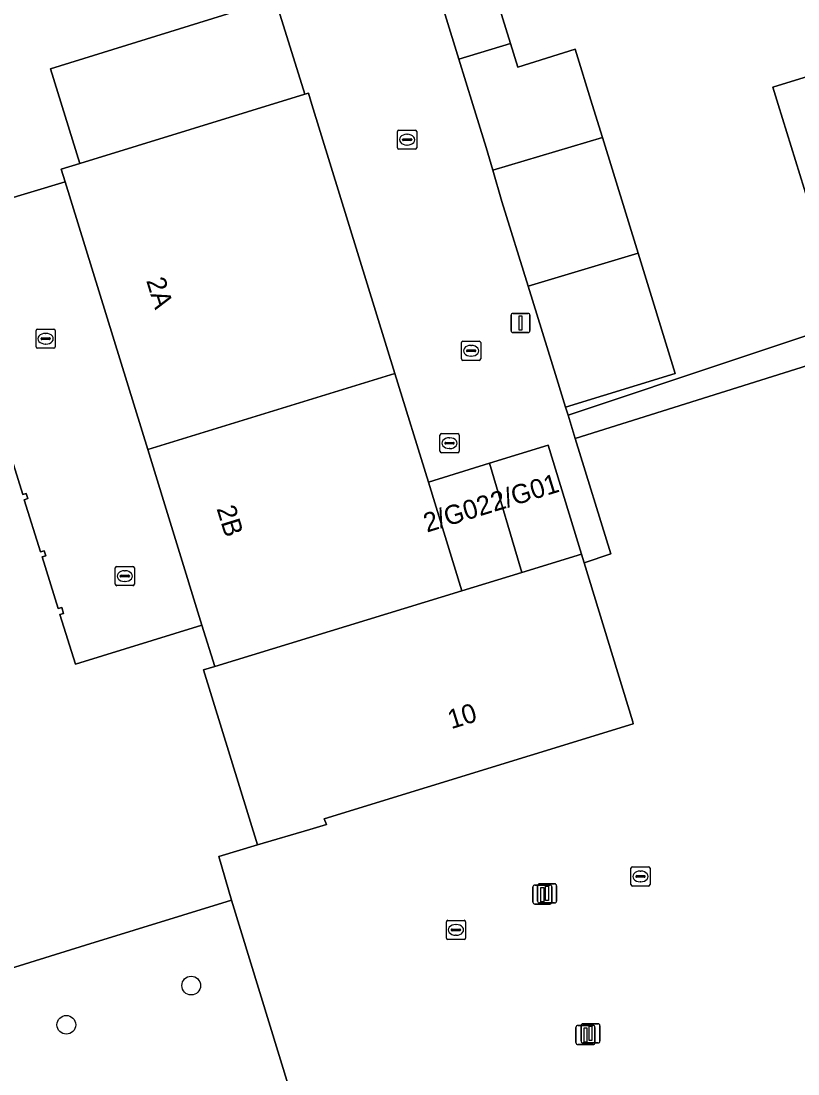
# Model space of a CAD drawing. Extents: x 161248 to 161848, y 384871 to 385383.
# Drawn here: x 161449.7 to 161490.3, y 384949.3 to 385004.4 of the extents above; entities that cross this region are included whole.
import ezdxf

# ---------------------------------------------------------------- set-up
doc = ezdxf.new("R2010")
doc.units = 0
for name, color, linetype in [('IMGEO_Boom', 7, 'Continuous'), ('IMGEO_Brandkraan', 7, 'Continuous'), ('IMGEO_Erf', 7, 'Continuous'), ('IMGEO_Groenvoorziening', 7, 'Continuous'), ('IMGEO_Hek', 7, 'Continuous'), ('IMGEO_Kolk', 7, 'Continuous'), ('IMGEO_Lichtmast', 7, 'Continuous'), ('IMGEO_Pand', 7, 'Continuous'), ('IMGEO_Pand_nummerreeks', 7, 'Continuous'), ('IMGEO_Parkeervlak_open', 7, 'Continuous'), ('IMGEO_Rijbaan_lokaal_open', 7, 'Continuous'), ('IMGEO_Voetpad_open', 7, 'Continuous')]:
    doc.layers.add(name, color=color, linetype=linetype)

msp = doc.modelspace()

# ---------------------------------------------------------------- linework, layer by layer
at = {"layer": 'IMGEO_Boom'}
for centre in [(161458.625, 384953.929), (161452.098, 384951.877)]:
    msp.add_circle(centre, 0.489, dxfattribs=at)
at = {"layer": 'IMGEO_Brandkraan'}
for p, q in [((161471.63, 384981.861), (161471.63, 384982.713)), ((161471.705, 384982.787), (161472.557, 384982.787)), ((161471.932, 384982.33), (161472.33, 384982.33)), ((161472.118, 384982.567), (161472.143, 384982.567)), ((161472.631, 384982.713), (161472.631, 384981.861)), ((161472.557, 384981.787), (161471.705, 384981.787)), ((161471.889, 384982.281), (161471.889, 384982.293)), ((161472.327, 384982.244), (161471.929, 384982.244)), ((161472.141, 384982.007), (161472.116, 384982.007)), ((161472.373, 384982.293), (161472.373, 384982.281))]:
    msp.add_line(p, q, dxfattribs=at)
for points in [[(161471.63, 384981.861), (161471.63, 384982.713)], [(161471.705, 384982.787), (161472.557, 384982.787)], [(161472.631, 384982.713), (161472.631, 384981.861)], [(161472.557, 384981.787), (161471.705, 384981.787)]]:
    msp.add_lwpolyline(points, dxfattribs=at)
for centre, radius, start, end in [((161471.707, 384982.711), 0.0765, 91.552, 178.448), ((161471.707, 384982.711), 0.0765, 91.552, 178.448), ((161471.929, 384982.29), 0.0403, 85.8775, 175.7526), ((161472.334, 384982.292), 0.0386, 1.7309, 96.639), ((161472.555, 384982.711), 0.0765, 1.552, 88.448), ((161472.555, 384982.711), 0.0765, 1.552, 88.448), ((161471.707, 384981.863), 0.0765, 181.552, 268.448), ((161471.707, 384981.863), 0.0765, 181.552, 268.448), ((161471.926, 384982.28), 0.0366, 178.938, 274.7102), ((161472.33, 384982.287), 0.043, 264.8664, 352.4533), ((161472.555, 384981.863), 0.0765, 271.552, 358.448), ((161472.555, 384981.863), 0.0765, 271.552, 358.448)]:
    msp.add_arc(centre, radius, start, end, dxfattribs=at)
for centre, major_axis, ratio, start_param, end_param in [((161472.117, 384982.287), (-0.387, 0.002), 0.722429, 4.712389, 7.853982), ((161472.142, 384982.287), (-0.39, 0.002), 0.717154, 1.570796, 4.712389)]:
    msp.add_ellipse(centre, major_axis=major_axis, ratio=ratio, start_param=start_param, end_param=end_param, dxfattribs=at)
at = {"layer": 'IMGEO_Erf'}
msp.add_lwpolyline([(161489.033, 385000.893), (161492.311, 385001.903), (161490.476, 385007.857), (161488.521, 385014.203), (161470.742, 385008.465), (161471.18, 385007.012), (161473.878, 385007.844), (161475.314, 385003.189), (161475.695, 385001.953), (161478.707, 385002.877), (161479.593, 385000), (161480.125, 384998.272), (161481.988, 384992.224), (161483.928, 384985.929), (161478.198, 384984.164), (161478.327, 384983.747), (161496.079, 384989.672), (161493.374, 384988.838), (161491.462, 384995.042), (161490.89, 384994.866), (161489.308, 385000)], close=True, dxfattribs=at)
msp.add_lwpolyline([(161504.48, 384990.635), (161478.706, 384982.523), (161480.569, 384976.5), (161479.172, 384976.026), (161481.71, 384967.719), (161481.734, 384967.62), (161465.577, 384962.651), (161465.703, 384962.356), (161464.826, 384962.094), (161462.094, 384961.279), (161460.068, 384960.675), (161460.725, 384958.4), (161468.671, 384932.496), (161456.058, 384928.282), (161456.306, 384927.519), (161458.229, 384921.594), (161459.445, 384917.85), (161459.563, 384917.873), (161460.304, 384915.459), (161465.803, 384917.137), (161465.842, 384917.432), (161470.469, 384917.199), (161473.166, 384917.063), (161500, 384915.713)], dxfattribs=at)
at = {"layer": 'IMGEO_Groenvoorziening'}
msp.add_lwpolyline([(161456.306, 384927.519), (161456.058, 384928.282), (161468.671, 384932.496), (161460.725, 384958.4), (161453.097, 384956.043), (161448.319, 384954.566), (161445.755, 384950.228), (161446.432, 384949.557), (161447.081, 384948.789), (161447.66, 384947.966), (161448.163, 384947.095), (161448.585, 384946.183), (161448.925, 384945.236), (161454.217, 384928.071), (161455.63, 384928.386), (161455.957, 384927.409)], close=True, dxfattribs=at)
at = {"layer": 'IMGEO_Hek'}
msp.add_lwpolyline([(161452.034, 384995.958), (161445.368, 384993.944)], dxfattribs=at)
at = {"layer": 'IMGEO_Kolk'}
for p, q in [((161469.413, 384997.728), (161469.413, 384998.58)), ((161469.488, 384998.654), (161470.34, 384998.654)), ((161469.901, 384998.434), (161469.926, 384998.434)), ((161470.414, 384998.58), (161470.414, 384997.728)), ((161469.672, 384998.148), (161469.672, 384998.16)), ((161470.11, 384998.111), (161469.712, 384998.111)), ((161469.715, 384998.197), (161470.113, 384998.197)), ((161469.924, 384997.874), (161469.899, 384997.874)), ((161470.156, 384998.16), (161470.156, 384998.148)), ((161470.34, 384997.654), (161469.488, 384997.654)), ((161450.516, 384987.322), (161450.516, 384988.174)), ((161450.591, 384988.248), (161451.443, 384988.248)), ((161451.004, 384988.028), (161451.029, 384988.028)), ((161451.517, 384988.174), (161451.517, 384987.322)), ((161450.775, 384987.742), (161450.775, 384987.754)), ((161451.213, 384987.705), (161450.815, 384987.705)), ((161450.818, 384987.791), (161451.216, 384987.791)), ((161451.027, 384987.468), (161451.002, 384987.468)), ((161451.259, 384987.754), (161451.259, 384987.742)), ((161472.758, 384986.689), (161472.758, 384987.541)), ((161472.833, 384987.615), (161473.685, 384987.615)), ((161473.246, 384987.395), (161473.271, 384987.395)), ((161473.759, 384987.541), (161473.759, 384986.689)), ((161451.443, 384987.248), (161450.591, 384987.248)), ((161473.017, 384987.109), (161473.017, 384987.121)), ((161473.455, 384987.072), (161473.057, 384987.072)), ((161473.06, 384987.158), (161473.458, 384987.158)), ((161473.269, 384986.835), (161473.244, 384986.835)), ((161473.501, 384987.121), (161473.501, 384987.109)), ((161473.685, 384986.615), (161472.833, 384986.615)), ((161454.655, 384974.911), (161454.655, 384975.763)), ((161454.73, 384975.837), (161455.582, 384975.837)), ((161455.656, 384975.763), (161455.656, 384974.911)), ((161454.914, 384975.331), (161454.914, 384975.343)), ((161455.352, 384975.294), (161454.954, 384975.294)), ((161454.957, 384975.38), (161455.355, 384975.38)), ((161455.143, 384975.617), (161455.168, 384975.617)), ((161455.398, 384975.343), (161455.398, 384975.331)), ((161455.582, 384974.837), (161454.73, 384974.837)), ((161455.166, 384975.057), (161455.141, 384975.057)), ((161481.613, 384959.207), (161481.613, 384960.059)), ((161481.688, 384960.133), (161482.54, 384960.133)), ((161482.101, 384959.913), (161482.126, 384959.913)), ((161482.614, 384960.059), (161482.614, 384959.207)), ((161481.872, 384959.627), (161481.872, 384959.639)), ((161482.31, 384959.59), (161481.912, 384959.59)), ((161481.915, 384959.676), (161482.313, 384959.676)), ((161482.124, 384959.353), (161482.099, 384959.353)), ((161482.356, 384959.639), (161482.356, 384959.627)), ((161482.54, 384959.133), (161481.688, 384959.133)), ((161471.965, 384956.414), (161471.965, 384957.266)), ((161472.04, 384957.34), (161472.892, 384957.34)), ((161472.453, 384957.12), (161472.478, 384957.12)), ((161472.966, 384957.266), (161472.966, 384956.414)), ((161472.224, 384956.834), (161472.224, 384956.846)), ((161472.662, 384956.797), (161472.264, 384956.797)), ((161472.267, 384956.883), (161472.665, 384956.883)), ((161472.476, 384956.56), (161472.451, 384956.56)), ((161472.708, 384956.846), (161472.708, 384956.834)), ((161472.892, 384956.34), (161472.04, 384956.34))]:
    msp.add_line(p, q, dxfattribs=at)
for points in [[(161469.413, 384997.728), (161469.413, 384998.58)], [(161469.488, 384998.654), (161470.34, 384998.654)], [(161470.414, 384998.58), (161470.414, 384997.728)], [(161470.34, 384997.654), (161469.488, 384997.654)], [(161450.516, 384987.322), (161450.516, 384988.174)], [(161450.591, 384988.248), (161451.443, 384988.248)], [(161451.517, 384988.174), (161451.517, 384987.322)], [(161472.758, 384986.689), (161472.758, 384987.541)], [(161472.833, 384987.615), (161473.685, 384987.615)], [(161473.759, 384987.541), (161473.759, 384986.689)], [(161451.443, 384987.248), (161450.591, 384987.248)], [(161473.685, 384986.615), (161472.833, 384986.615)], [(161454.655, 384974.911), (161454.655, 384975.763)], [(161454.73, 384975.837), (161455.582, 384975.837)], [(161455.656, 384975.763), (161455.656, 384974.911)], [(161455.582, 384974.837), (161454.73, 384974.837)], [(161481.613, 384959.207), (161481.613, 384960.059)], [(161481.688, 384960.133), (161482.54, 384960.133)], [(161482.614, 384960.059), (161482.614, 384959.207)], [(161482.54, 384959.133), (161481.688, 384959.133)], [(161471.965, 384956.414), (161471.965, 384957.266)], [(161472.04, 384957.34), (161472.892, 384957.34)], [(161472.966, 384957.266), (161472.966, 384956.414)], [(161472.892, 384956.34), (161472.04, 384956.34)]]:
    msp.add_lwpolyline(points, dxfattribs=at)
for centre, radius, start, end in [((161469.49, 384998.578), 0.0765, 91.552, 178.448), ((161469.49, 384998.578), 0.0765, 91.552, 178.448), ((161470.338, 384998.578), 0.0765, 1.552, 88.448), ((161470.338, 384998.578), 0.0765, 1.552, 88.448), ((161469.712, 384998.157), 0.0403, 85.8775, 175.7526), ((161469.709, 384998.147), 0.0366, 178.938, 274.7102), ((161470.113, 384998.154), 0.043, 264.8664, 352.4533), ((161470.117, 384998.159), 0.0386, 1.7309, 96.639), ((161469.49, 384997.73), 0.0765, 181.552, 268.448), ((161469.49, 384997.73), 0.0765, 181.552, 268.448), ((161470.338, 384997.73), 0.0765, 271.552, 358.448), ((161470.338, 384997.73), 0.0765, 271.552, 358.448), ((161450.593, 384988.172), 0.0765, 91.552, 178.448), ((161450.593, 384988.172), 0.0765, 91.552, 178.448), ((161451.441, 384988.172), 0.0765, 1.552, 88.448), ((161451.441, 384988.172), 0.0765, 1.552, 88.448), ((161450.593, 384987.324), 0.0765, 181.552, 268.448), ((161450.593, 384987.324), 0.0765, 181.552, 268.448), ((161450.815, 384987.751), 0.0403, 85.8775, 175.7526), ((161450.812, 384987.741), 0.0366, 178.938, 274.7102), ((161451.216, 384987.748), 0.043, 264.8664, 352.4533), ((161451.22, 384987.753), 0.0386, 1.7309, 96.639), ((161451.441, 384987.324), 0.0765, 271.552, 358.448), ((161451.441, 384987.324), 0.0765, 271.552, 358.448), ((161472.835, 384987.539), 0.0765, 91.552, 178.448), ((161472.835, 384987.539), 0.0765, 91.552, 178.448), ((161473.683, 384987.539), 0.0765, 1.552, 88.448), ((161473.683, 384987.539), 0.0765, 1.552, 88.448), ((161473.057, 384987.118), 0.0403, 85.8775, 175.7526), ((161473.054, 384987.108), 0.0366, 178.938, 274.7102), ((161473.458, 384987.115), 0.043, 264.8664, 352.4533), ((161473.462, 384987.12), 0.0386, 1.7309, 96.639), ((161472.835, 384986.691), 0.0765, 181.552, 268.448), ((161472.835, 384986.691), 0.0765, 181.552, 268.448), ((161473.683, 384986.691), 0.0765, 271.552, 358.448), ((161473.683, 384986.691), 0.0765, 271.552, 358.448), ((161454.732, 384975.761), 0.0765, 91.552, 178.448), ((161454.732, 384975.761), 0.0765, 91.552, 178.448), ((161455.58, 384975.761), 0.0765, 1.552, 88.448), ((161455.58, 384975.761), 0.0765, 1.552, 88.448), ((161454.954, 384975.34), 0.0403, 85.8775, 175.7526), ((161454.951, 384975.33), 0.0366, 178.938, 274.7102), ((161455.355, 384975.337), 0.043, 264.8664, 352.4533), ((161455.359, 384975.342), 0.0386, 1.7309, 96.639), ((161454.732, 384974.913), 0.0765, 181.552, 268.448), ((161454.732, 384974.913), 0.0765, 181.552, 268.448), ((161455.58, 384974.913), 0.0765, 271.552, 358.448), ((161455.58, 384974.913), 0.0765, 271.552, 358.448), ((161481.69, 384960.057), 0.0765, 91.552, 178.448), ((161481.69, 384960.057), 0.0765, 91.552, 178.448), ((161482.538, 384960.057), 0.0765, 1.552, 88.448), ((161482.538, 384960.057), 0.0765, 1.552, 88.448), ((161481.69, 384959.209), 0.0765, 181.552, 268.448), ((161481.69, 384959.209), 0.0765, 181.552, 268.448), ((161481.912, 384959.636), 0.0403, 85.8775, 175.7526), ((161481.909, 384959.626), 0.0366, 178.938, 274.7102), ((161482.313, 384959.633), 0.043, 264.8664, 352.4533), ((161482.317, 384959.638), 0.0386, 1.7309, 96.639), ((161482.538, 384959.209), 0.0765, 271.552, 358.448), ((161482.538, 384959.209), 0.0765, 271.552, 358.448), ((161472.042, 384957.264), 0.0765, 91.552, 178.448), ((161472.042, 384957.264), 0.0765, 91.552, 178.448), ((161472.89, 384957.264), 0.0765, 1.552, 88.448), ((161472.89, 384957.264), 0.0765, 1.552, 88.448), ((161472.264, 384956.843), 0.0403, 85.8775, 175.7526), ((161472.261, 384956.833), 0.0366, 178.938, 274.7102), ((161472.665, 384956.84), 0.043, 264.8664, 352.4533), ((161472.669, 384956.845), 0.0386, 1.7309, 96.639), ((161472.042, 384956.416), 0.0765, 181.552, 268.448), ((161472.042, 384956.416), 0.0765, 181.552, 268.448), ((161472.89, 384956.416), 0.0765, 271.552, 358.448), ((161472.89, 384956.416), 0.0765, 271.552, 358.448)]:
    msp.add_arc(centre, radius, start, end, dxfattribs=at)
for centre, major_axis, ratio, start_param, end_param in [((161469.9, 384998.154), (-0.387, 0.002), 0.722429, 4.712389, 7.853982), ((161469.925, 384998.154), (-0.39, 0.002), 0.717154, 1.570796, 4.712389), ((161451.003, 384987.748), (-0.387, 0.002), 0.722429, 4.712389, 7.853982), ((161451.028, 384987.748), (-0.39, 0.002), 0.717154, 1.570796, 4.712389), ((161473.245, 384987.115), (-0.387, 0.002), 0.722429, 4.712389, 7.853982), ((161473.27, 384987.115), (-0.39, 0.002), 0.717154, 1.570796, 4.712389), ((161455.142, 384975.337), (-0.387, 0.002), 0.722429, 4.712389, 7.853982), ((161455.167, 384975.337), (-0.39, 0.002), 0.717154, 1.570796, 4.712389), ((161482.1, 384959.633), (-0.387, 0.002), 0.722429, 4.712389, 7.853982), ((161482.125, 384959.633), (-0.39, 0.002), 0.717154, 1.570796, 4.712389), ((161472.452, 384956.84), (-0.387, 0.002), 0.722429, 4.712389, 7.853982), ((161472.477, 384956.84), (-0.39, 0.002), 0.717154, 1.570796, 4.712389)]:
    msp.add_ellipse(centre, major_axis=major_axis, ratio=ratio, start_param=start_param, end_param=end_param, dxfattribs=at)
at = {"layer": 'IMGEO_Lichtmast'}
for p, q in [((161475.347, 384988.172), (161475.347, 384988.972)), ((161475.347, 384988.972), (161475.347, 384988.172)), ((161475.447, 384989.072), (161476.237, 384989.072)), ((161476.237, 384989.072), (161475.447, 384989.072)), ((161476.337, 384988.972), (161476.337, 384988.172)), ((161476.337, 384988.172), (161476.337, 384988.972)), ((161476.237, 384988.072), (161475.447, 384988.072)), ((161475.447, 384988.072), (161476.237, 384988.072)), ((161476.834, 384959.25), (161477.624, 384959.25)), ((161477.624, 384959.25), (161476.834, 384959.25)), ((161476.491, 384958.287), (161476.491, 384959.087)), ((161476.491, 384959.087), (161476.491, 384958.287)), ((161476.591, 384959.187), (161477.381, 384959.187)), ((161477.381, 384959.187), (161476.591, 384959.187)), ((161476.734, 384958.35), (161476.734, 384959.15)), ((161476.734, 384959.15), (161476.734, 384958.35)), ((161477.481, 384959.087), (161477.481, 384958.287)), ((161477.481, 384958.287), (161477.481, 384959.087)), ((161477.724, 384959.15), (161477.724, 384958.35)), ((161477.724, 384958.35), (161477.724, 384959.15)), ((161477.381, 384958.187), (161476.591, 384958.187)), ((161476.591, 384958.187), (161477.381, 384958.187)), ((161477.624, 384958.25), (161476.834, 384958.25)), ((161476.834, 384958.25), (161477.624, 384958.25)), ((161478.741, 384950.945), (161478.741, 384951.745)), ((161478.741, 384951.745), (161478.741, 384950.945)), ((161478.841, 384951.845), (161479.631, 384951.845)), ((161479.631, 384951.845), (161478.841, 384951.845)), ((161479.004, 384951.032), (161479.004, 384951.832)), ((161479.004, 384951.832), (161479.004, 384951.032)), ((161479.104, 384951.932), (161479.894, 384951.932)), ((161479.894, 384951.932), (161479.104, 384951.932)), ((161479.731, 384951.745), (161479.731, 384950.945)), ((161479.731, 384950.945), (161479.731, 384951.745)), ((161479.994, 384951.832), (161479.994, 384951.032)), ((161479.994, 384951.032), (161479.994, 384951.832)), ((161479.631, 384950.845), (161478.841, 384950.845)), ((161478.841, 384950.845), (161479.631, 384950.845)), ((161479.894, 384950.932), (161479.104, 384950.932)), ((161479.104, 384950.932), (161479.894, 384950.932))]:
    msp.add_line(p, q, dxfattribs=at)
for points in [[(161475.767, 384988.947), (161475.917, 384988.947), (161475.917, 384988.197), (161475.767, 384988.197), (161475.767, 384988.947)], [(161476.911, 384959.062), (161477.061, 384959.062), (161477.061, 384958.312), (161476.911, 384958.312), (161476.911, 384959.062)], [(161477.154, 384959.125), (161477.304, 384959.125), (161477.304, 384958.375), (161477.154, 384958.375), (161477.154, 384959.125)], [(161479.161, 384951.72), (161479.311, 384951.72), (161479.311, 384950.97), (161479.161, 384950.97), (161479.161, 384951.72)], [(161479.424, 384951.807), (161479.574, 384951.807), (161479.574, 384951.057), (161479.424, 384951.057), (161479.424, 384951.807)]]:
    msp.add_lwpolyline(points, dxfattribs=at)
for centre, start, end in [((161475.447, 384988.972), 90, 180), ((161475.447, 384988.972), 90, 180), ((161476.237, 384988.972), 0, 90), ((161476.237, 384988.972), 360, 90), ((161475.447, 384988.172), 180, 270), ((161475.447, 384988.172), 180, 270), ((161476.237, 384988.172), 270, 0), ((161476.237, 384988.172), 270, 0), ((161476.834, 384959.15), 90, 180), ((161476.834, 384959.15), 90, 180), ((161477.624, 384959.15), 0, 90), ((161477.624, 384959.15), 360, 90), ((161476.591, 384959.087), 90, 180), ((161476.591, 384959.087), 90, 180), ((161477.381, 384959.087), 0, 90), ((161477.381, 384959.087), 360, 90), ((161476.591, 384958.287), 180, 270), ((161476.591, 384958.287), 180, 270), ((161476.834, 384958.35), 180, 270), ((161476.834, 384958.35), 180, 270), ((161477.381, 384958.287), 270, 0), ((161477.381, 384958.287), 270, 0), ((161477.624, 384958.35), 270, 0), ((161477.624, 384958.35), 270, 0), ((161478.841, 384951.745), 90, 180), ((161478.841, 384951.745), 90, 180), ((161479.104, 384951.832), 90, 180), ((161479.104, 384951.832), 90, 180), ((161479.631, 384951.745), 0, 90), ((161479.631, 384951.745), 360, 90), ((161479.894, 384951.832), 0, 90), ((161479.894, 384951.832), 360, 90), ((161478.841, 384950.945), 180, 270), ((161478.841, 384950.945), 180, 270), ((161479.104, 384951.032), 180, 270), ((161479.104, 384951.032), 180, 270), ((161479.631, 384950.945), 270, 0), ((161479.631, 384950.945), 270, 0), ((161479.894, 384951.032), 270, 0), ((161479.894, 384951.032), 270, 0)]:
    msp.add_arc(centre, 0.1, start, end, dxfattribs=at)
at = {"layer": 'IMGEO_Pand'}
for points in [[(161472.616, 385002.358), (161475.314, 385003.189), (161473.878, 385007.844), (161471.18, 385007.012)], [(161501.619, 385000), (161500.299, 385004.283), (161500, 385004.194), (161492.311, 385001.903), (161489.033, 385000.893), (161489.308, 385000), (161490.89, 384994.866), (161491.462, 384995.042), (161494.168, 384995.875), (161500, 384997.623), (161502.147, 384998.285)], [(161473.343, 385000), (161474.039, 384997.742), (161474.387, 384996.562), (161480.125, 384998.272), (161479.593, 385000), (161478.707, 385002.877), (161475.695, 385001.953), (161475.314, 385003.189), (161472.616, 385002.358)], [(161464.932, 385000), (161464.749, 385000.592), (161464.574, 385000.538), (161452.809, 384996.909), (161451.834, 384996.608), (161452.034, 384995.958), (161456.356, 384981.952), (161469.271, 384985.935)], [(161474.872, 384994.919), (161476.238, 384990.501), (161481.988, 384992.224), (161480.125, 384998.272), (161474.387, 384996.562)], [(161477.739, 384985.648), (161478.198, 384984.164), (161483.928, 384985.929), (161481.988, 384992.224), (161476.238, 384990.501)], [(161459.19, 384972.767), (161459.854, 384970.611), (161472.777, 384974.572), (161471.025, 384980.249), (161469.271, 384985.935), (161456.356, 384981.952)], [(161477.285, 384982.181), (161474.212, 384981.233), (161475.908, 384975.532), (161479.03, 384976.489)], [(161474.212, 384981.233), (161471.025, 384980.249), (161472.777, 384974.572), (161475.908, 384975.532)], [(161465.703, 384962.356), (161465.577, 384962.651), (161481.734, 384967.62), (161481.71, 384967.719), (161479.172, 384976.026), (161479.03, 384976.489), (161475.908, 384975.532), (161472.777, 384974.572), (161459.854, 384970.611), (161459.27, 384970.432), (161462.094, 384961.279), (161464.826, 384962.094)]]:
    msp.add_lwpolyline(points, close=True, dxfattribs=at)
msp.add_lwpolyline([(161448.319, 384954.566), (161453.097, 384956.043), (161460.725, 384958.4), (161460.068, 384960.675), (161462.094, 384961.279), (161459.27, 384970.432), (161459.854, 384970.611), (161459.19, 384972.767), (161452.569, 384970.725), (161451.762, 384973.325), (161451.953, 384973.385), (161451.855, 384973.703), (161451.664, 384973.644), (161450.828, 384976.339), (161451.019, 384976.399), (161450.939, 384976.656), (161450.748, 384976.597), (161449.9, 384979.332), (161450.091, 384979.392), (161450.006, 384979.664), (161449.815, 384979.605), (161448.998, 384982.236)], dxfattribs=at)
at = {"layer": 'IMGEO_Parkeervlak_open'}
msp.add_lwpolyline([(161464.574, 385000.538), (161463.019, 385005.524), (161451.266, 385001.859), (161452.809, 384996.909)], close=True, dxfattribs=at)
at = {"layer": 'IMGEO_Rijbaan_lokaal_open'}
for points in [[(161445.368, 384993.944), (161452.034, 384995.958), (161451.834, 384996.608), (161452.809, 384996.909), (161451.266, 385001.859), (161463.019, 385005.524), (161464.574, 385000.538), (161464.749, 385000.592), (161464.932, 385000), (161469.271, 384985.935), (161471.025, 384980.249), (161474.212, 384981.233), (161477.285, 384982.181), (161479.03, 384976.489), (161479.172, 384976.026), (161480.569, 384976.5), (161478.706, 384982.523), (161478.327, 384983.747), (161478.198, 384984.164), (161477.739, 384985.648), (161476.238, 384990.501), (161474.872, 384994.919), (161474.387, 384996.562), (161474.039, 384997.742), (161473.343, 385000), (161472.616, 385002.358), (161471.18, 385007.012)], [(161448.998, 384982.236), (161449.815, 384979.605), (161450.006, 384979.664), (161450.091, 384979.392), (161449.9, 384979.332), (161450.748, 384976.597), (161450.939, 384976.656), (161451.019, 384976.399), (161450.828, 384976.339), (161451.664, 384973.644), (161451.855, 384973.703), (161451.953, 384973.385), (161451.762, 384973.325), (161452.569, 384970.725), (161459.19, 384972.767), (161456.356, 384981.952), (161452.034, 384995.958), (161445.368, 384993.944)]]:
    msp.add_lwpolyline(points, dxfattribs=at)
at = {"layer": 'IMGEO_Voetpad_open'}
msp.add_lwpolyline([(161504.48, 384990.635), (161504.045, 384992.126), (161500, 384990.881), (161499.267, 384990.655), (161496.079, 384989.672), (161478.327, 384983.747), (161478.706, 384982.523)], close=True, dxfattribs=at)

# ---------------------------------------------------------------- texts
at = {"layer": 'IMGEO_Pand_nummerreeks'}
for s, rotation, p in [('2A', 287.1484, (161456.266, 384990.791)), ('2/G01', 17.1516, (161474.456, 384978.692)), ('2/G02', 17.1516, (161470.947, 384977.609)), ('2B', 287.1474, (161459.944, 384978.871)), ('10', 17.095, (161472.218, 384967.33))]:
    msp.add_text(s, height=1, rotation=rotation, dxfattribs=at).set_placement(p)

doc.saveas('drawing.dxf')
